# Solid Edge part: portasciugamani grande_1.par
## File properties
Last saved by: i.fialdini
Revision: 62
Tipo di contenuto documento: 0
Accuracy: 0.990
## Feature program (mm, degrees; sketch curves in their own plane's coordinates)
body "unnamed Body 1"
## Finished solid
Body 1: solid body, 10 faces, 24 edges, 16 vertices.
  Faces by surface: plane 7, cylinder 3
  Edges by curve: line 18, circle 6
Bounding box of the edges (mm): 45.000 x 386.500 x 2.000, from (-343.5, -210, -147) to (-298.5, 176.5, -145).
Cylindrical faces by radius (mm): R5 x2, R33.5 x1
Planar faces by outward normal: +x 2, +y 1, +z 1, -x 2, -z 1
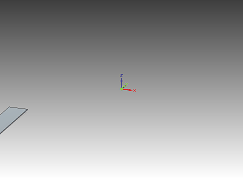
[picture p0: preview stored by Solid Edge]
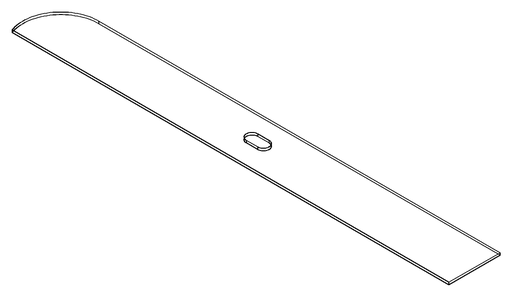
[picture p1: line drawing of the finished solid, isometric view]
